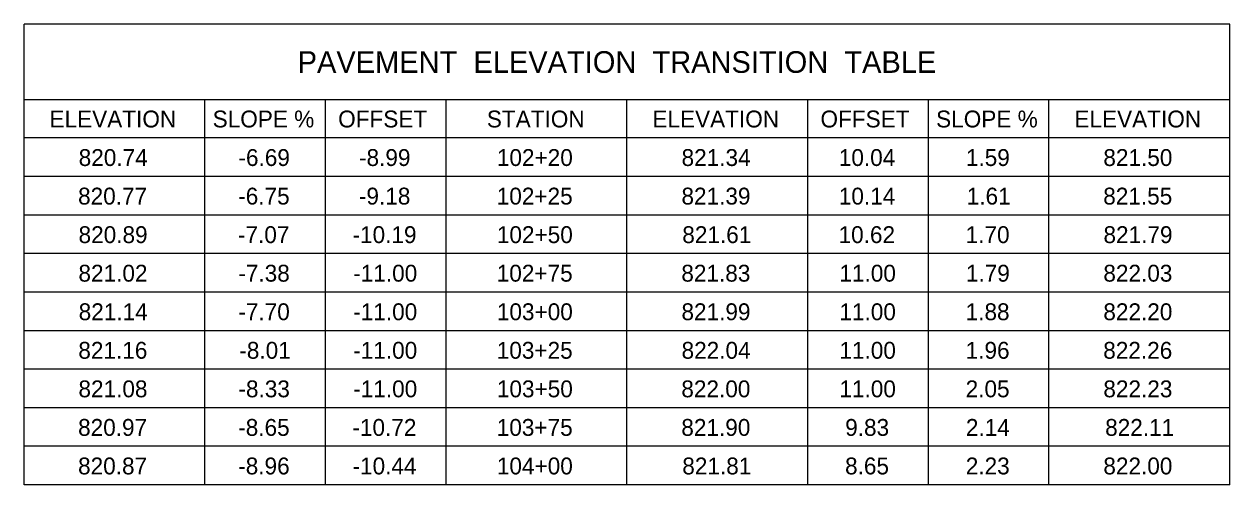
# Model space of a CAD drawing. Extents: x -189 to 370, y -316 to 69.
# Drawn here: x 4.78 to 14.78, y 43.09 to 46.92 of the extents above; entities that cross this region are included whole.
import ezdxf

# ---------------------------------------------------------------- set-up
doc = ezdxf.new("R2010")
doc.units = 0
for name, color, linetype in [('Default', 7, 'Continuous'), ('SH_Text', 7, 'Continuous'), ('ST_Text', 7, 'Continuous')]:
    doc.layers.add(name, color=color, linetype=linetype)

msp = doc.modelspace()

# ---------------------------------------------------------------- linework, layer by layer
at = {"layer": 'SH_Text'}
for p, q in [((14.775, 46.918), (4.775, 46.918)), ((4.775, 43.093), (4.775, 46.918)), ((14.775, 43.093), (14.775, 46.918)), ((14.775, 46.288), (4.775, 46.288)), ((12.775, 46.288), (5.775, 46.288)), ((6.275, 45.973), (6.275, 46.288)), ((7.275, 45.973), (7.275, 46.288)), ((8.275, 45.973), (8.275, 46.288)), ((9.775, 45.909), (9.775, 46.288)), ((11.275, 45.973), (11.275, 46.288)), ((12.275, 45.973), (12.275, 46.288)), ((13.275, 45.973), (13.275, 46.288)), ((14.775, 45.973), (4.775, 45.973)), ((6.275, 43.093), (6.275, 45.973)), ((7.275, 43.093), (7.275, 45.973)), ((8.275, 43.093), (8.275, 45.973)), ((9.775, 43.093), (9.775, 45.973)), ((11.275, 43.093), (11.275, 45.973)), ((12.275, 43.093), (12.275, 45.973)), ((13.275, 43.093), (13.275, 45.973)), ((14.775, 45.653), (4.775, 45.653)), ((14.775, 45.333), (4.775, 45.333)), ((14.775, 45.013), (4.775, 45.013)), ((14.775, 44.693), (4.775, 44.693)), ((14.775, 44.373), (4.775, 44.373)), ((14.775, 44.053), (4.775, 44.053)), ((14.775, 43.733), (4.775, 43.733)), ((14.775, 43.413), (4.775, 43.413)), ((14.775, 43.093), (4.775, 43.093))]:
    msp.add_line(p, q, dxfattribs=at)

# ---------------------------------------------------------------- texts
at = {"layer": 'Default'}
for s, p in [('ELEVATION', (4.986, 46.06)), ('SLOPE %', (6.339, 46.06)), ('OFFSET', (7.38, 46.06)), ('STATION', (8.613, 46.06)), ('ELEVATION', (9.986, 46.06)), ('OFFSET', (11.38, 46.06)), ('SLOPE %', (12.339, 46.06)), ('ELEVATION', (13.486, 46.06)), ('820.74', (5.228, 45.74)), ('-6.69', (6.553, 45.74)), ('-8.99', (7.553, 45.74)), ('102+20', (8.696, 45.74)), ('821.34', (10.228, 45.74)), ('10.04', (11.532, 45.74)), ('1.59', (12.586, 45.74)), ('821.50', (13.726, 45.74)), ('820.77', (5.223, 45.42)), ('-6.75', (6.551, 45.42)), ('-9.18', (7.552, 45.42)), ('102+25', (8.695, 45.42)), ('821.39', (10.227, 45.42)), ('10.14', (11.532, 45.42)), ('1.61', (12.593, 45.42)), ('821.55', (13.725, 45.42)), ('820.89', (5.227, 45.1)), ('-7.07', (6.549, 45.1)), ('-10.19', (7.499, 45.1)), ('102+50', (8.696, 45.1)), ('821.61', (10.234, 45.1)), ('10.62', (11.53, 45.1)), ('1.70', (12.584, 45.1)), ('821.79', (13.727, 45.1)), ('821.02', (5.226, 44.78)), ('-7.38', (6.552, 44.78)), ('-11.00', (7.505, 44.78)), ('102+75', (8.695, 44.78)), ('821.83', (10.226, 44.78)), ('11.00', (11.537, 44.78)), ('1.79', (12.586, 44.78)), ('822.03', (13.726, 44.78)), ('821.14', (5.228, 44.46)), ('-7.70', (6.552, 44.46)), ('-11.00', (7.505, 44.46)), ('103+00', (8.696, 44.46)), ('821.99', (10.227, 44.46)), ('11.00', (11.537, 44.46)), ('1.88', (12.584, 44.46)), ('822.20', (13.726, 44.46)), ('821.16', (5.225, 44.14)), ('-8.01', (6.56, 44.14)), ('-11.00', (7.505, 44.14)), ('103+25', (8.695, 44.14)), ('822.04', (10.228, 44.14)), ('11.00', (11.537, 44.14)), ('1.96', (12.584, 44.14)), ('822.26', (13.725, 44.14)), ('821.08', (5.226, 43.82)), ('-8.33', (6.553, 43.82)), ('-11.00', (7.505, 43.82)), ('103+50', (8.696, 43.82)), ('822.00', (10.226, 43.82)), ('11.00', (11.537, 43.82)), ('2.05', (12.584, 43.82)), ('822.23', (13.726, 43.82)), ('820.97', (5.223, 43.5)), ('-8.65', (6.551, 43.5)), ('-10.72', (7.498, 43.5)), ('103+75', (8.695, 43.5)), ('821.90', (10.226, 43.5)), ('9.83', (11.585, 43.5)), ('2.14', (12.586, 43.5)), ('822.11', (13.741, 43.5)), ('820.87', (5.223, 43.18)), ('-8.96', (6.551, 43.18)), ('-10.44', (7.499, 43.18)), ('104+00', (8.696, 43.18)), ('821.81', (10.234, 43.18)), ('8.65', (11.584, 43.18)), ('2.23', (12.585, 43.18)), ('822.00', (13.726, 43.18))]:
    msp.add_text(s, height=0.14, dxfattribs=at).set_placement(p)
at = {"layer": 'ST_Text'}
msp.add_text('PAVEMENT  ELEVATION  TRANSITION  TABLE', height=0.18, dxfattribs=at).set_placement((7.044, 46.513))

doc.saveas('drawing.dxf')
